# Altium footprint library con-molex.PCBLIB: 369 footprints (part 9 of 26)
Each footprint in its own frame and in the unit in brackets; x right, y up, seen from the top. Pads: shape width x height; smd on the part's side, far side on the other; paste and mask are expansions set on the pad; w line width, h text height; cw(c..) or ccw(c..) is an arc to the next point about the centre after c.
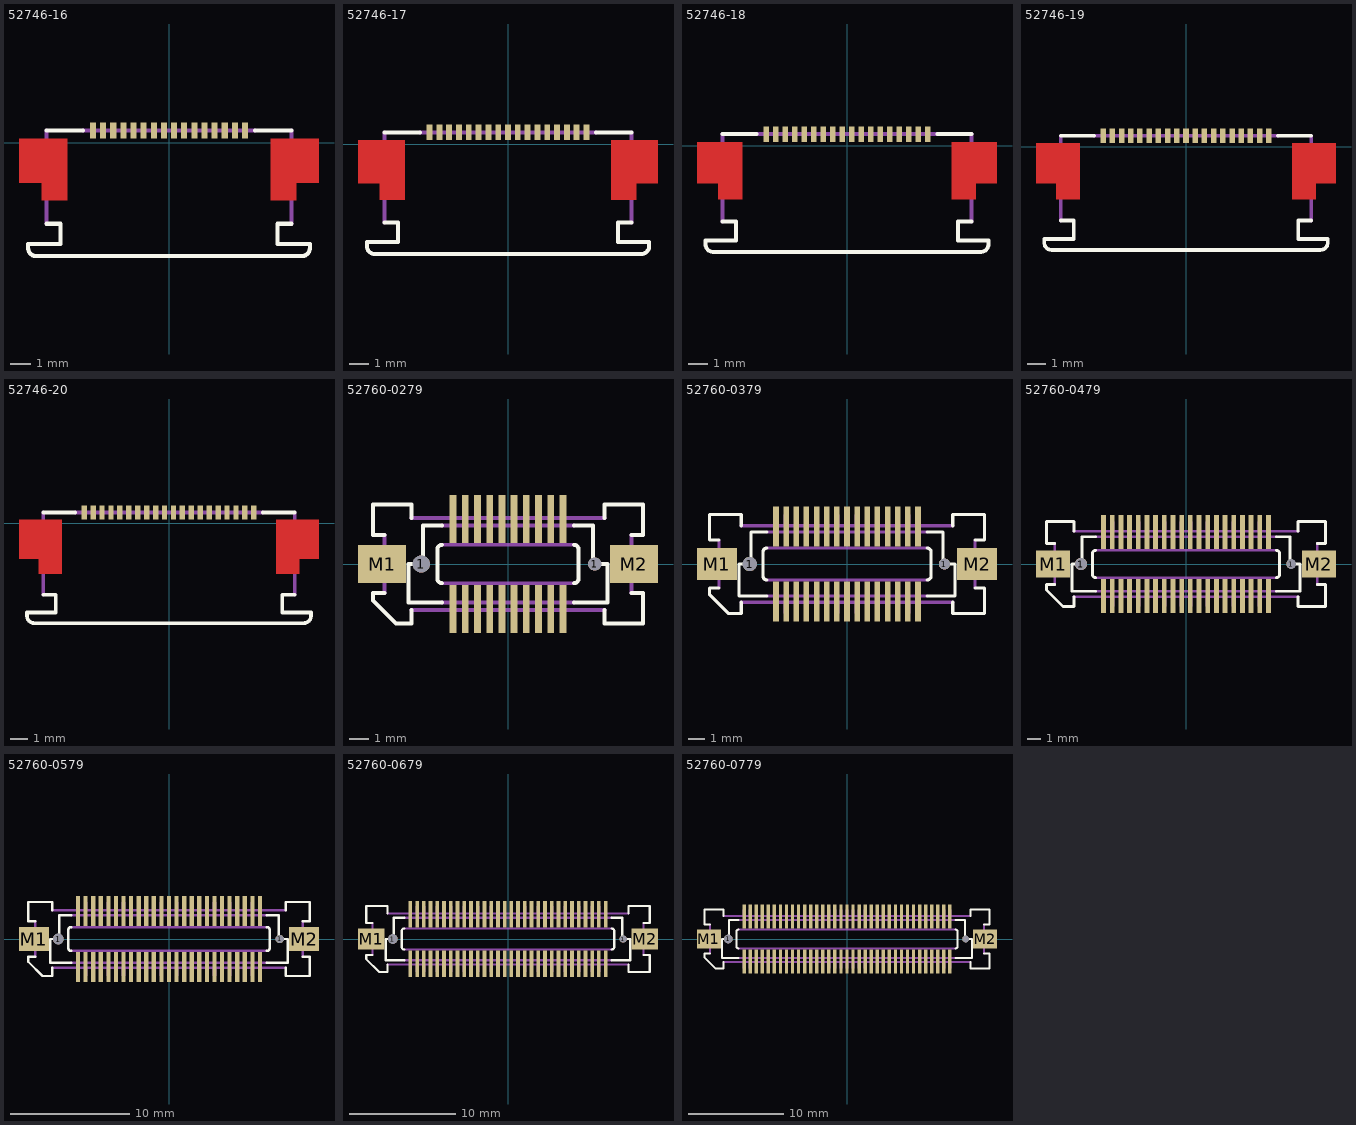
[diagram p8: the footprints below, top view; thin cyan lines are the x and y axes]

## 52746-16 [mil]
pads (16):
  rect 11.81x31.5 smd: 1(-147.64,23.62) 2(-127.95,23.62) 3(-108.27,23.62) 4(-88.58,23.62) 5(-68.9,23.62) 6(-49.21,23.62) 7(-29.53,23.62) 8(-9.84,23.62) 9(9.84,23.62) 10(29.53,23.62) 11(49.21,23.62) 12(68.9,23.62) 13(88.58,23.62) 14(108.27,23.62) 15(127.95,23.62) 16(147.64,23.62)
Top Layer:
  rectangle: -291.34,-78.74 -196.85,7.87
  rectangle: -248.03,-112.2 -196.85,-78.74
  rectangle: 196.85,-78.74 291.34,7.87
  rectangle: 196.85,-112.2 248.03,-78.74
Top Overlay:
  lines w8: -238.19,-157.48 -210.63,-157.48 -210.63,-196.85 -273.62,-196.85 -273.62,-204.72 ccw(c-257.87,-204.72) -257.87,-220.47 257.87,-220.47 ccw(c257.87,-204.72) 273.62,-204.72 273.62,-196.85 210.63,-196.85 210.63,-157.48 238.19,-157.48 ; -238.19,23.62 -167.32,23.62 ; 167.32,23.62 238.19,23.62
Top Paste:
  rectangle: -286.42,-74.8 -200.79,2.95
  rectangle: -244.09,-108.27 -200.79,-74.8
  rectangle: 200.79,-74.8 286.42,2.95
  rectangle: 200.79,-108.27 244.09,-74.8
Top Solder:
  rectangle: -291.34,-78.74 -196.85,7.87
  rectangle: -248.03,-112.2 -196.85,-78.74
  rectangle: 196.85,-78.74 291.34,7.87
  rectangle: 196.85,-112.2 248.03,-78.74
  rectangle: -154.53,6.89 -140.75,40.35
  rectangle: -134.84,6.89 -121.06,40.35
  rectangle: -115.16,6.89 -101.38,40.35
  rectangle: -95.47,6.89 -81.69,40.35
  rectangle: -75.79,6.89 -62.01,40.35
  rectangle: -56.1,6.89 -42.32,40.35
  rectangle: -36.42,6.89 -22.64,40.35
  rectangle: -16.73,6.89 -2.95,40.35
  rectangle: 2.95,6.89 16.73,40.35
  rectangle: 22.64,6.89 36.42,40.35
  rectangle: 42.32,6.89 56.1,40.35
  rectangle: 62.01,6.89 75.79,40.35
  rectangle: 81.69,6.89 95.47,40.35
  rectangle: 101.38,6.89 115.16,40.35
  rectangle: 121.06,6.89 134.84,40.35
  rectangle: 140.75,6.89 154.53,40.35
Mechanical 16:
  lines w8: -238.19,-157.48 -238.19,23.62 ; -167.32,23.62 167.32,23.62 ; 238.19,-157.48 238.19,23.62
  lines w19.69: -275.59,-55.12 -244.09,-55.12 -244.09,-9.84 -275.59,-9.84 ; 275.59,-55.12 244.09,-55.12 244.09,-9.84 275.59,-9.84

## 52746-17 [mil]
pads (17):
  rect 11.81x31.5 smd: 1(-157.48,23.62) 2(-137.8,23.62) 3(-118.11,23.62) 4(-98.43,23.62) 5(-78.74,23.62) 6(-59.06,23.62) 7(-39.37,23.62) 8(-19.69,23.62) 9(0,23.62) 10(19.69,23.62) 11(39.37,23.62) 12(59.06,23.62) 13(78.74,23.62) 14(98.43,23.62) 15(118.11,23.62) 16(137.8,23.62) 17(157.48,23.62)
Top Layer:
  rectangle: -301.18,-78.74 -206.69,7.87
  rectangle: -257.87,-112.2 -206.69,-78.74
  rectangle: 206.69,-78.74 301.18,7.87
  rectangle: 206.69,-112.2 257.87,-78.74
Top Overlay:
  lines w8: -248.03,-157.48 -220.47,-157.48 -220.47,-196.85 -283.46,-196.85 -283.46,-204.72 ccw(c-267.71,-204.72) -267.72,-220.47 267.72,-220.47 ccw(c267.71,-204.72) 283.46,-204.72 283.46,-196.85 220.47,-196.85 220.47,-157.48 248.03,-157.48 ; -248.03,23.62 -177.17,23.62 ; 177.17,23.62 248.03,23.62
Top Paste:
  rectangle: -296.26,-74.8 -210.63,2.95
  rectangle: -253.94,-108.27 -210.63,-74.8
  rectangle: 210.63,-74.8 296.26,2.95
  rectangle: 210.63,-108.27 253.94,-74.8
Top Solder:
  rectangle: -301.18,-78.74 -206.69,7.87
  rectangle: -257.87,-112.2 -206.69,-78.74
  rectangle: 206.69,-78.74 301.18,7.87
  rectangle: 206.69,-112.2 257.87,-78.74
  rectangle: -164.37,6.89 -150.59,40.35
  rectangle: -144.69,6.89 -130.91,40.35
  rectangle: -125,6.89 -111.22,40.35
  rectangle: -105.32,6.89 -91.54,40.35
  rectangle: -85.63,6.89 -71.85,40.35
  rectangle: -65.94,6.89 -52.17,40.35
  rectangle: -46.26,6.89 -32.48,40.35
  rectangle: -26.57,6.89 -12.8,40.35
  rectangle: -6.89,6.89 6.89,40.35
  rectangle: 12.8,6.89 26.57,40.35
  rectangle: 32.48,6.89 46.26,40.35
  rectangle: 52.17,6.89 65.94,40.35
  rectangle: 71.85,6.89 85.63,40.35
  rectangle: 91.54,6.89 105.32,40.35
  rectangle: 111.22,6.89 125,40.35
  rectangle: 130.91,6.89 144.69,40.35
  rectangle: 150.59,6.89 164.37,40.35
Mechanical 16:
  lines w8: -248.03,-157.48 -248.03,23.62 ; -177.17,23.62 177.17,23.62 ; 248.03,-157.48 248.03,23.62
  lines w19.69: -285.43,-55.12 -253.94,-55.12 -253.94,-9.84 -285.43,-9.84 ; 285.43,-55.12 253.94,-55.12 253.94,-9.84 285.43,-9.84

## 52746-18 [mil]
pads (18):
  rect 11.81x31.5 smd: 1(-167.32,23.62) 2(-147.64,23.62) 3(-127.95,23.62) 4(-108.27,23.62) 5(-88.58,23.62) 6(-68.9,23.62) 7(-49.21,23.62) 8(-29.53,23.62) 9(-9.84,23.62) 10(9.84,23.62) 11(29.53,23.62) 12(49.21,23.62) 13(68.9,23.62) 14(88.58,23.62) 15(108.27,23.62) 16(127.95,23.62) 17(147.64,23.62) 18(167.32,23.62)
Top Layer:
  rectangle: -311.02,-78.74 -216.54,7.87
  rectangle: -267.72,-112.2 -216.54,-78.74
  rectangle: 216.54,-78.74 311.02,7.87
  rectangle: 216.54,-112.2 267.72,-78.74
Top Overlay:
  lines w8: -257.87,-157.48 -230.32,-157.48 -230.32,-196.85 -293.31,-196.85 -293.31,-204.72 ccw(c-277.56,-204.72) -277.56,-220.47 277.56,-220.47 ccw(c277.56,-204.72) 293.31,-204.72 293.31,-196.85 230.32,-196.85 230.32,-157.48 257.87,-157.48 ; -257.87,23.62 -187.01,23.62 ; 187.01,23.62 257.87,23.62
Top Paste:
  rectangle: -306.1,-74.8 -220.47,2.95
  rectangle: -263.78,-108.27 -220.47,-74.8
  rectangle: 220.47,-74.8 306.1,2.95
  rectangle: 220.47,-108.27 263.78,-74.8
Top Solder:
  rectangle: -311.02,-78.74 -216.54,7.87
  rectangle: -267.72,-112.2 -216.54,-78.74
  rectangle: 216.54,-78.74 311.02,7.87
  rectangle: 216.54,-112.2 267.72,-78.74
  rectangle: -174.21,6.89 -160.43,40.35
  rectangle: -154.53,6.89 -140.75,40.35
  rectangle: -134.84,6.89 -121.06,40.35
  rectangle: -115.16,6.89 -101.38,40.35
  rectangle: -95.47,6.89 -81.69,40.35
  rectangle: -75.79,6.89 -62.01,40.35
  rectangle: -56.1,6.89 -42.32,40.35
  rectangle: -36.42,6.89 -22.64,40.35
  rectangle: -16.73,6.89 -2.95,40.35
  rectangle: 2.95,6.89 16.73,40.35
  rectangle: 22.64,6.89 36.42,40.35
  rectangle: 42.32,6.89 56.1,40.35
  rectangle: 62.01,6.89 75.79,40.35
  rectangle: 81.69,6.89 95.47,40.35
  rectangle: 101.38,6.89 115.16,40.35
  rectangle: 121.06,6.89 134.84,40.35
  rectangle: 140.75,6.89 154.53,40.35
  rectangle: 160.43,6.89 174.21,40.35
Mechanical 16:
  lines w8: -257.87,-157.48 -257.87,23.62 ; -187.01,23.62 187.01,23.62 ; 257.87,-157.48 257.87,23.62
  lines w19.69: -295.28,-55.12 -263.78,-55.12 -263.78,-9.84 -295.28,-9.84 ; 295.28,-55.12 263.78,-55.12 263.78,-9.84 295.28,-9.84

## 52746-19 [mil]
pads (19):
  rect 11.81x31.5 smd: 1(-177.17,23.62) 2(-157.48,23.62) 3(-137.8,23.62) 4(-118.11,23.62) 5(-98.43,23.62) 6(-78.74,23.62) 7(-59.06,23.62) 8(-39.37,23.62) 9(-19.69,23.62) 10(0,23.62) 11(19.69,23.62) 12(39.37,23.62) 13(59.06,23.62) 14(78.74,23.62) 15(98.43,23.62) 16(118.11,23.62) 17(137.8,23.62) 18(157.48,23.62) 19(177.17,23.62)
Top Layer:
  rectangle: -320.87,-78.74 -226.38,7.87
  rectangle: -277.56,-112.2 -226.38,-78.74
  rectangle: 226.38,-78.74 320.87,7.87
  rectangle: 226.38,-112.2 277.56,-78.74
Top Overlay:
  lines w8: -267.72,-157.48 -240.16,-157.48 -240.16,-196.85 -303.15,-196.85 -303.15,-204.72 ccw(c-287.4,-204.72) -287.4,-220.47 287.4,-220.47 ccw(c287.4,-204.72) 303.15,-204.72 303.15,-196.85 240.16,-196.85 240.16,-157.48 267.72,-157.48 ; -267.72,23.62 -196.85,23.62 ; 196.85,23.62 267.72,23.62
Top Paste:
  rectangle: -315.94,-74.8 -230.32,2.95
  rectangle: -273.62,-108.27 -230.32,-74.8
  rectangle: 230.32,-74.8 315.94,2.95
  rectangle: 230.32,-108.27 273.62,-74.8
Top Solder:
  rectangle: -320.87,-78.74 -226.38,7.87
  rectangle: -277.56,-112.2 -226.38,-78.74
  rectangle: 226.38,-78.74 320.87,7.87
  rectangle: 226.38,-112.2 277.56,-78.74
  rectangle: -184.06,6.89 -170.28,40.35
  rectangle: -164.37,6.89 -150.59,40.35
  rectangle: -144.69,6.89 -130.91,40.35
  rectangle: -125,6.89 -111.22,40.35
  rectangle: -105.32,6.89 -91.54,40.35
  rectangle: -85.63,6.89 -71.85,40.35
  rectangle: -65.94,6.89 -52.17,40.35
  rectangle: -46.26,6.89 -32.48,40.35
  rectangle: -26.57,6.89 -12.8,40.35
  rectangle: -6.89,6.89 6.89,40.35
  rectangle: 12.8,6.89 26.57,40.35
  rectangle: 32.48,6.89 46.26,40.35
  rectangle: 52.17,6.89 65.94,40.35
  rectangle: 71.85,6.89 85.63,40.35
  rectangle: 91.54,6.89 105.32,40.35
  rectangle: 111.22,6.89 125,40.35
  rectangle: 130.91,6.89 144.69,40.35
  rectangle: 150.59,6.89 164.37,40.35
  rectangle: 170.28,6.89 184.06,40.35
Mechanical 16:
  lines w8: -267.72,-157.48 -267.72,23.62 ; -196.85,23.62 196.85,23.62 ; 267.72,-157.48 267.72,23.62
  lines w19.69: -305.12,-55.12 -273.62,-55.12 -273.62,-9.84 -305.12,-9.84 ; 305.12,-55.12 273.62,-55.12 273.62,-9.84 305.12,-9.84

## 52746-20 [mil]
pads (20):
  rect 11.81x31.5 smd: 1(-187.01,23.62) 2(-167.32,23.62) 3(-147.64,23.62) 4(-127.95,23.62) 5(-108.27,23.62) 6(-88.58,23.62) 7(-68.9,23.62) 8(-49.21,23.62) 9(-29.53,23.62) 10(-9.84,23.62) 11(9.84,23.62) 12(29.53,23.62) 13(49.21,23.62) 14(68.9,23.62) 15(88.58,23.62) 16(108.27,23.62) 17(127.95,23.62) 18(147.64,23.62) 19(167.32,23.62) 20(187.01,23.62)
Top Layer:
  rectangle: -330.71,-78.74 -236.22,7.87
  rectangle: -287.4,-112.2 -236.22,-78.74
  rectangle: 236.22,-78.74 330.71,7.87
  rectangle: 236.22,-112.2 287.4,-78.74
Top Overlay:
  lines w8: -277.56,-157.48 -250,-157.48 -250,-196.85 -312.99,-196.85 -312.99,-204.72 ccw(c-297.24,-204.72) -297.24,-220.47 297.24,-220.47 ccw(c297.24,-204.72) 312.99,-204.72 312.99,-196.85 250,-196.85 250,-157.48 277.56,-157.48 ; -277.56,23.62 -206.69,23.62 ; 206.69,23.62 277.56,23.62
Top Paste:
  rectangle: -325.79,-74.8 -240.16,2.95
  rectangle: -283.46,-108.27 -240.16,-74.8
  rectangle: 240.16,-74.8 325.79,2.95
  rectangle: 240.16,-108.27 283.46,-74.8
Top Solder:
  rectangle: -330.71,-78.74 -236.22,7.87
  rectangle: -287.4,-112.2 -236.22,-78.74
  rectangle: 236.22,-78.74 330.71,7.87
  rectangle: 236.22,-112.2 287.4,-78.74
  rectangle: -193.9,6.89 -180.12,40.35
  rectangle: -174.21,6.89 -160.43,40.35
  rectangle: -154.53,6.89 -140.75,40.35
  rectangle: -134.84,6.89 -121.06,40.35
  rectangle: -115.16,6.89 -101.38,40.35
  rectangle: -95.47,6.89 -81.69,40.35
  rectangle: -75.79,6.89 -62.01,40.35
  rectangle: -56.1,6.89 -42.32,40.35
  rectangle: -36.42,6.89 -22.64,40.35
  rectangle: -16.73,6.89 -2.95,40.35
  rectangle: 2.95,6.89 16.73,40.35
  rectangle: 22.64,6.89 36.42,40.35
  rectangle: 42.32,6.89 56.1,40.35
  rectangle: 62.01,6.89 75.79,40.35
  rectangle: 81.69,6.89 95.47,40.35
  rectangle: 101.38,6.89 115.16,40.35
  rectangle: 121.06,6.89 134.84,40.35
  rectangle: 140.75,6.89 154.53,40.35
  rectangle: 160.43,6.89 174.21,40.35
  rectangle: 180.12,6.89 193.9,40.35
Mechanical 16:
  lines w8: -277.56,-157.48 -277.56,23.62 ; -206.69,23.62 206.69,23.62 ; 277.56,-157.48 277.56,23.62
  lines w19.69: -314.96,-55.12 -283.46,-55.12 -283.46,-9.84 -314.96,-9.84 ; 314.96,-55.12 283.46,-55.12 283.46,-9.84 314.96,-9.84

## 52760-0279 [mm]
pads (24):
  round 0.9 hole 0.9: 1(-4.51,0)
  rect 0.35x2.5 smd: 1(-2.857,-2.35) 2(-2.857,2.35) 3(-2.222,-2.35) 4(-2.222,2.35) 5(-1.587,-2.35) 6(-1.587,2.35) 7(-0.953,-2.35) 8(-0.953,2.35) 9(-0.318,-2.35) 10(-0.318,2.35) 11(0.318,-2.35) 12(0.318,2.35) 13(0.953,-2.35) 14(0.953,2.35) 15(1.587,-2.35) 16(1.587,2.35) 17(2.222,-2.35) 18(2.222,2.35) 19(2.857,-2.35) 20(2.857,2.35)
  round 0.7 hole 0.7: 1(4.51,0)
  rect 2.5x2 smd: M1(-6.55,0) M2(6.55,0)
Top Overlay:
  lines w0.203: -6.425,-1.5 -7.025,-1.5 -7.025,-1.9 -5.825,-3.1 -5.025,-3.1 -5.025,-2.4 ; -6.425,1.5 -7.025,1.5 -7.025,3.1 -5.025,3.1 -5.025,2.4 ; -3.425,-2 -5.175,-2 -5.175,0 -4.425,0 -4.425,2 -3.425,2 ; -3.425,-1 cw(c-3.425,-0.75) -3.675,-0.75 -3.675,0.75 cw(c-3.425,0.75) -3.425,1 ; 3.425,-2 5.175,-2 5.175,0 4.425,0 4.425,2 3.425,2 ; 3.425,-1 ccw(c3.425,-0.75) 3.675,-0.75 3.675,0.75 ccw(c3.425,0.75) 3.425,1 ; 5.025,-2.4 5.025,-3.1 7.025,-3.1 7.025,-1.5 6.425,-1.5 ; 5.025,2.4 5.025,3.1 7.025,3.1 7.025,1.5 6.425,1.5
Top Solder:
  rectangle: -3.057,-3.625 -2.658,-1.075
  region: -2.658,3.625 -3.057,3.625 -3.057,1.075 -2.658,1.075
  rectangle: -2.422,-3.625 -2.023,-1.075
  region: -2.023,3.625 -2.422,3.625 -2.422,1.075 -2.023,1.075
  rectangle: -1.787,-3.625 -1.388,-1.075
  region: -1.388,3.625 -1.787,3.625 -1.787,1.075 -1.388,1.075
  rectangle: -1.152,-3.625 -0.753,-1.075
  region: -0.753,3.625 -1.152,3.625 -1.152,1.075 -0.753,1.075
  rectangle: -0.517,-3.625 -0.118,-1.075
  region: -0.118,3.625 -0.517,3.625 -0.517,1.075 -0.118,1.075
  rectangle: 0.118,-3.625 0.517,-1.075
  region: 0.517,3.625 0.118,3.625 0.118,1.075 0.517,1.075
  rectangle: 0.753,-3.625 1.152,-1.075
  region: 1.152,3.625 0.753,3.625 0.753,1.075 1.152,1.075
  rectangle: 1.388,-3.625 1.787,-1.075
  region: 1.787,3.625 1.388,3.625 1.388,1.075 1.787,1.075
  rectangle: 2.023,-3.625 2.422,-1.075
  region: 2.422,3.625 2.023,3.625 2.023,1.075 2.422,1.075
  rectangle: 2.658,-3.625 3.057,-1.075
  region: 3.057,3.625 2.658,3.625 2.658,1.075 3.057,1.075
Mechanical 16:
  rectangle: -3.008,-3.1 -2.707,-2.375
  region: -2.707,3.1 -3.008,3.1 -3.008,2.375 -2.707,2.375
  rectangle: -2.373,-3.1 -2.072,-2.375
  region: -2.072,3.1 -2.373,3.1 -2.373,2.375 -2.072,2.375
  rectangle: -1.738,-3.1 -1.437,-2.375
  region: -1.437,3.1 -1.738,3.1 -1.738,2.375 -1.437,2.375
  rectangle: -1.103,-3.1 -0.802,-2.375
  region: -0.802,3.1 -1.103,3.1 -1.103,2.375 -0.802,2.375
  rectangle: -0.468,-3.1 -0.167,-2.375
  region: -0.167,3.1 -0.468,3.1 -0.468,2.375 -0.167,2.375
  rectangle: 0.167,-3.1 0.468,-2.375
  region: 0.468,3.1 0.167,3.1 0.167,2.375 0.468,2.375
  rectangle: 0.802,-3.1 1.103,-2.375
  region: 1.103,3.1 0.802,3.1 0.802,2.375 1.103,2.375
  rectangle: 1.437,-3.1 1.738,-2.375
  region: 1.738,3.1 1.437,3.1 1.437,2.375 1.738,2.375
  rectangle: 2.072,-3.1 2.373,-2.375
  region: 2.373,3.1 2.072,3.1 2.072,2.375 2.373,2.375
  rectangle: 2.707,-3.1 3.008,-2.375
  region: 3.008,3.1 2.707,3.1 2.707,2.375 3.008,2.375
  lines w0.203: -6.425,-1.5 -6.425,1.5 ; -5.025,-2.4 5.025,-2.4 ; -5.025,2.4 5.025,2.4 ; -3.425,-2 3.425,-2 ; -3.425,-1 3.425,-1 ; -3.425,1 3.425,1 ; -3.425,2 3.425,2 ; 6.425,-1.5 6.425,1.5

## 52760-0379 [mm]
pads (34):
  round 0.9 hole 0.9: 1(-6.098,0)
  rect 0.35x2.5 smd: 1(-4.445,-2.35) 2(-4.445,2.35) 3(-3.81,-2.35) 4(-3.81,2.35) 5(-3.175,-2.35) 6(-3.175,2.35) 7(-2.54,-2.35) 8(-2.54,2.35) 9(-1.905,-2.35) 10(-1.905,2.35) 11(-1.27,-2.35) 12(-1.27,2.35) 13(-0.635,-2.35) 14(-0.635,2.35) 15(0,-2.35) 16(0,2.35) 17(0.635,-2.35) 18(0.635,2.35) 19(1.27,-2.35) 20(1.27,2.35) 21(1.905,-2.35) 22(1.905,2.35) 23(2.54,-2.35) 24(2.54,2.35) 25(3.175,-2.35) 26(3.175,2.35) 27(3.81,-2.35) 28(3.81,2.35) 29(4.445,-2.35) 30(4.445,2.35)
  round 0.7 hole 0.7: 1(6.098,0)
  rect 2.5x2 smd: M1(-8.137,0) M2(8.137,0)
Top Overlay:
  lines w0.203: -8.012,-1.5 -8.612,-1.5 -8.612,-1.9 -7.412,-3.1 -6.612,-3.1 -6.612,-2.4 ; -8.012,1.5 -8.612,1.5 -8.612,3.1 -6.612,3.1 -6.612,2.4 ; -5.012,-2 -6.762,-2 -6.762,0 -6.012,0 -6.012,2 -5.012,2 ; -5.012,-1 cw(c-5.013,-0.75) -5.263,-0.75 -5.263,0.75 cw(c-5.013,0.75) -5.012,1 ; 5.012,-2 6.762,-2 6.762,0 6.012,0 6.012,2 5.012,2 ; 5.012,-1 ccw(c5.013,-0.75) 5.263,-0.75 5.263,0.75 ccw(c5.013,0.75) 5.012,1 ; 6.612,-2.4 6.612,-3.1 8.612,-3.1 8.612,-1.5 8.012,-1.5 ; 6.612,2.4 6.612,3.1 8.612,3.1 8.612,1.5 8.012,1.5
Top Solder:
  region: 4.645,3.625 4.245,3.625 4.245,1.075 4.645,1.075
  rectangle: 4.245,-3.625 4.645,-1.075
  region: 4.01,3.625 3.61,3.625 3.61,1.075 4.01,1.075
  rectangle: 3.61,-3.625 4.01,-1.075
  region: 3.375,3.625 2.975,3.625 2.975,1.075 3.375,1.075
  rectangle: 2.975,-3.625 3.375,-1.075
  region: 2.74,3.625 2.34,3.625 2.34,1.075 2.74,1.075
  rectangle: 2.34,-3.625 2.74,-1.075
  region: 2.105,3.625 1.705,3.625 1.705,1.075 2.105,1.075
  rectangle: 1.705,-3.625 2.105,-1.075
  region: 1.47,3.625 1.07,3.625 1.07,1.075 1.47,1.075
  rectangle: 1.07,-3.625 1.47,-1.075
  region: 0.835,3.625 0.435,3.625 0.435,1.075 0.835,1.075
  rectangle: 0.435,-3.625 0.835,-1.075
  region: 0.2,3.625 -0.2,3.625 -0.2,1.075 0.2,1.075
  rectangle: -0.2,-3.625 0.2,-1.075
  region: -0.435,3.625 -0.835,3.625 -0.835,1.075 -0.435,1.075
  rectangle: -0.835,-3.625 -0.435,-1.075
  region: -1.07,3.625 -1.47,3.625 -1.47,1.075 -1.07,1.075
  rectangle: -1.47,-3.625 -1.07,-1.075
  region: -1.705,3.625 -2.105,3.625 -2.105,1.075 -1.705,1.075
  rectangle: -2.105,-3.625 -1.705,-1.075
  region: -2.34,3.625 -2.74,3.625 -2.74,1.075 -2.34,1.075
  rectangle: -2.74,-3.625 -2.34,-1.075
  region: -2.975,3.625 -3.375,3.625 -3.375,1.075 -2.975,1.075
  rectangle: -3.375,-3.625 -2.975,-1.075
  region: -3.61,3.625 -4.01,3.625 -4.01,1.075 -3.61,1.075
  rectangle: -4.01,-3.625 -3.61,-1.075
  region: -4.245,3.625 -4.645,3.625 -4.645,1.075 -4.245,1.075
  rectangle: -4.645,-3.625 -4.245,-1.075
Mechanical 16:
  region: 4.595,3.1 4.295,3.1 4.295,2.375 4.595,2.375
  rectangle: 4.295,-3.1 4.595,-2.375
  region: 3.96,3.1 3.66,3.1 3.66,2.375 3.96,2.375
  rectangle: 3.66,-3.1 3.96,-2.375
  region: 3.325,3.1 3.025,3.1 3.025,2.375 3.325,2.375
  rectangle: 3.025,-3.1 3.325,-2.375
  region: 2.69,3.1 2.39,3.1 2.39,2.375 2.69,2.375
  rectangle: 2.39,-3.1 2.69,-2.375
  region: 2.055,3.1 1.755,3.1 1.755,2.375 2.055,2.375
  rectangle: 1.755,-3.1 2.055,-2.375
  region: 1.42,3.1 1.12,3.1 1.12,2.375 1.42,2.375
  rectangle: 1.12,-3.1 1.42,-2.375
  region: 0.785,3.1 0.485,3.1 0.485,2.375 0.785,2.375
  rectangle: 0.485,-3.1 0.785,-2.375
  region: 0.15,3.1 -0.15,3.1 -0.15,2.375 0.15,2.375
  rectangle: -0.15,-3.1 0.15,-2.375
  region: -0.485,3.1 -0.785,3.1 -0.785,2.375 -0.485,2.375
  rectangle: -0.785,-3.1 -0.485,-2.375
  region: -1.12,3.1 -1.42,3.1 -1.42,2.375 -1.12,2.375
  rectangle: -1.42,-3.1 -1.12,-2.375
  region: -1.755,3.1 -2.055,3.1 -2.055,2.375 -1.755,2.375
  rectangle: -2.055,-3.1 -1.755,-2.375
  region: -2.39,3.1 -2.69,3.1 -2.69,2.375 -2.39,2.375
  rectangle: -2.69,-3.1 -2.39,-2.375
  region: -3.025,3.1 -3.325,3.1 -3.325,2.375 -3.025,2.375
  rectangle: -3.325,-3.1 -3.025,-2.375
  region: -3.66,3.1 -3.96,3.1 -3.96,2.375 -3.66,2.375
  rectangle: -3.96,-3.1 -3.66,-2.375
  region: -4.295,3.1 -4.595,3.1 -4.595,2.375 -4.295,2.375
  rectangle: -4.595,-3.1 -4.295,-2.375
  lines w0.203: -8.012,-1.5 -8.012,1.5 ; -6.612,-2.4 6.612,-2.4 ; -6.612,2.4 6.612,2.4 ; -5.012,-2 5.012,-2 ; -5.012,-1 5.012,-1 ; -5.012,1 5.012,1 ; -5.012,2 5.012,2 ; 8.012,-1.5 8.012,1.5

## 52760-0479 [mm]
pads (44):
  round 0.9 hole 0.9: 1(-7.685,0)
  rect 0.35x2.5 smd: 1(-6.032,-2.35) 2(-6.032,2.35) 3(-5.397,-2.35) 4(-5.397,2.35) 5(-4.763,-2.35) 6(-4.763,2.35) 7(-4.127,-2.35) 8(-4.127,2.35) 9(-3.492,-2.35) 10(-3.492,2.35) 11(-2.857,-2.35) 12(-2.857,2.35) 13(-2.222,-2.35) 14(-2.222,2.35) 15(-1.587,-2.35) 16(-1.587,2.35) 17(-0.953,-2.35) 18(-0.953,2.35) 19(-0.318,-2.35) 20(-0.318,2.35) 21(0.318,-2.35) 22(0.318,2.35) 23(0.953,-2.35) 24(0.953,2.35) 25(1.587,-2.35) 26(1.587,2.35) 27(2.222,-2.35) 28(2.222,2.35) 29(2.857,-2.35) 30(2.857,2.35) 31(3.492,-2.35) 32(3.492,2.35) 33(4.127,-2.35) 34(4.127,2.35) 35(4.763,-2.35) 36(4.763,2.35) 37(5.397,-2.35) 38(5.397,2.35) 39(6.032,-2.35) 40(6.032,2.35)
  round 0.7 hole 0.7: 1(7.685,0)
  rect 2.5x2 smd: M1(-9.725,0) M2(9.725,0)
Top Overlay:
  lines w0.203: -9.6,-1.5 -10.2,-1.5 -10.2,-1.9 -9,-3.1 -8.2,-3.1 -8.2,-2.4 ; -9.6,1.5 -10.2,1.5 -10.2,3.1 -8.2,3.1 -8.2,2.4 ; -6.6,-2 -8.35,-2 -8.35,0 -7.6,0 -7.6,2 -6.6,2 ; -6.6,-1 cw(c-6.6,-0.75) -6.85,-0.75 -6.85,0.75 cw(c-6.6,0.75) -6.6,1 ; 6.6,-2 8.35,-2 8.35,0 7.6,0 7.6,2 6.6,2 ; 6.6,-1 ccw(c6.6,-0.75) 6.85,-0.75 6.85,0.75 ccw(c6.6,0.75) 6.6,1 ; 8.2,-2.4 8.2,-3.1 10.2,-3.1 10.2,-1.5 9.6,-1.5 ; 8.2,2.4 8.2,3.1 10.2,3.1 10.2,1.5 9.6,1.5
Top Solder:
  rectangle: -6.232,-3.625 -5.833,-1.075
  region: -5.833,3.625 -6.232,3.625 -6.232,1.075 -5.833,1.075
  rectangle: -5.597,-3.625 -5.198,-1.075
  region: -5.198,3.625 -5.597,3.625 -5.597,1.075 -5.198,1.075
  rectangle: -4.962,-3.625 -4.563,-1.075
  region: -4.563,3.625 -4.962,3.625 -4.962,1.075 -4.563,1.075
  rectangle: -4.327,-3.625 -3.928,-1.075
  region: -3.928,3.625 -4.327,3.625 -4.327,1.075 -3.928,1.075
  rectangle: -3.692,-3.625 -3.293,-1.075
  region: -3.293,3.625 -3.692,3.625 -3.692,1.075 -3.293,1.075
  rectangle: -3.057,-3.625 -2.658,-1.075
  region: -2.658,3.625 -3.057,3.625 -3.057,1.075 -2.658,1.075
  rectangle: -2.422,-3.625 -2.023,-1.075
  region: -2.023,3.625 -2.422,3.625 -2.422,1.075 -2.023,1.075
  rectangle: -1.787,-3.625 -1.388,-1.075
  region: -1.388,3.625 -1.787,3.625 -1.787,1.075 -1.388,1.075
  rectangle: -1.152,-3.625 -0.753,-1.075
  region: -0.753,3.625 -1.152,3.625 -1.152,1.075 -0.753,1.075
  rectangle: -0.517,-3.625 -0.118,-1.075
  region: -0.118,3.625 -0.517,3.625 -0.517,1.075 -0.118,1.075
  rectangle: 0.118,-3.625 0.517,-1.075
  region: 0.517,3.625 0.118,3.625 0.118,1.075 0.517,1.075
  rectangle: 0.753,-3.625 1.152,-1.075
  region: 1.152,3.625 0.753,3.625 0.753,1.075 1.152,1.075
  rectangle: 1.388,-3.625 1.787,-1.075
  region: 1.787,3.625 1.388,3.625 1.388,1.075 1.787,1.075
  rectangle: 2.023,-3.625 2.422,-1.075
  region: 2.422,3.625 2.023,3.625 2.023,1.075 2.422,1.075
  rectangle: 2.658,-3.625 3.057,-1.075
  region: 3.057,3.625 2.658,3.625 2.658,1.075 3.057,1.075
  rectangle: 3.293,-3.625 3.692,-1.075
  region: 3.692,3.625 3.293,3.625 3.293,1.075 3.692,1.075
  rectangle: 3.928,-3.625 4.327,-1.075
  region: 4.327,3.625 3.928,3.625 3.928,1.075 4.327,1.075
  rectangle: 4.563,-3.625 4.962,-1.075
  region: 4.962,3.625 4.563,3.625 4.563,1.075 4.962,1.075
  rectangle: 5.198,-3.625 5.597,-1.075
  region: 5.597,3.625 5.198,3.625 5.198,1.075 5.597,1.075
  rectangle: 5.833,-3.625 6.232,-1.075
  region: 6.232,3.625 5.833,3.625 5.833,1.075 6.232,1.075
Mechanical 16:
  rectangle: -6.183,-3.1 -5.882,-2.375
  region: -5.882,3.1 -6.183,3.1 -6.183,2.375 -5.882,2.375
  rectangle: -5.548,-3.1 -5.247,-2.375
  region: -5.247,3.1 -5.548,3.1 -5.548,2.375 -5.247,2.375
  rectangle: -4.913,-3.1 -4.612,-2.375
  region: -4.612,3.1 -4.913,3.1 -4.913,2.375 -4.612,2.375
  rectangle: -4.278,-3.1 -3.977,-2.375
  region: -3.977,3.1 -4.278,3.1 -4.278,2.375 -3.977,2.375
  rectangle: -3.643,-3.1 -3.342,-2.375
  region: -3.342,3.1 -3.643,3.1 -3.643,2.375 -3.342,2.375
  rectangle: -3.008,-3.1 -2.707,-2.375
  region: -2.707,3.1 -3.008,3.1 -3.008,2.375 -2.707,2.375
  rectangle: -2.373,-3.1 -2.072,-2.375
  region: -2.072,3.1 -2.373,3.1 -2.373,2.375 -2.072,2.375
  rectangle: -1.738,-3.1 -1.437,-2.375
  region: -1.437,3.1 -1.738,3.1 -1.738,2.375 -1.437,2.375
  rectangle: -1.103,-3.1 -0.802,-2.375
  region: -0.802,3.1 -1.103,3.1 -1.103,2.375 -0.802,2.375
  rectangle: -0.468,-3.1 -0.167,-2.375
  region: -0.167,3.1 -0.468,3.1 -0.468,2.375 -0.167,2.375
  rectangle: 0.167,-3.1 0.468,-2.375
  region: 0.468,3.1 0.167,3.1 0.167,2.375 0.468,2.375
  rectangle: 0.802,-3.1 1.103,-2.375
  region: 1.103,3.1 0.802,3.1 0.802,2.375 1.103,2.375
  rectangle: 1.437,-3.1 1.738,-2.375
  region: 1.738,3.1 1.437,3.1 1.437,2.375 1.738,2.375
  rectangle: 2.072,-3.1 2.373,-2.375
  region: 2.373,3.1 2.072,3.1 2.072,2.375 2.373,2.375
  rectangle: 2.707,-3.1 3.008,-2.375
  region: 3.008,3.1 2.707,3.1 2.707,2.375 3.008,2.375
  rectangle: 3.342,-3.1 3.643,-2.375
  region: 3.643,3.1 3.342,3.1 3.342,2.375 3.643,2.375
  rectangle: 3.977,-3.1 4.278,-2.375
  region: 4.278,3.1 3.977,3.1 3.977,2.375 4.278,2.375
  rectangle: 4.612,-3.1 4.913,-2.375
  region: 4.913,3.1 4.612,3.1 4.612,2.375 4.913,2.375
  rectangle: 5.247,-3.1 5.548,-2.375
  region: 5.548,3.1 5.247,3.1 5.247,2.375 5.548,2.375
  rectangle: 5.882,-3.1 6.183,-2.375
  region: 6.183,3.1 5.882,3.1 5.882,2.375 6.183,2.375
  lines w0.203: -9.6,-1.5 -9.6,1.5 ; -8.2,-2.4 8.2,-2.4 ; -8.2,2.4 8.2,2.4 ; -6.6,-2 6.6,-2 ; -6.6,-1 6.6,-1 ; -6.6,1 6.6,1 ; -6.6,2 6.6,2 ; 9.6,-1.5 9.6,1.5

## 52760-0579 [mm]
pads (54):
  round 0.9 hole 0.9: 1(-9.273,0)
  rect 0.35x2.5 smd: 1(-7.62,-2.35) 2(-7.62,2.35) 3(-6.985,-2.35) 4(-6.985,2.35) 5(-6.35,-2.35) 6(-6.35,2.35) 7(-5.715,-2.35) 8(-5.715,2.35) 9(-5.08,-2.35) 10(-5.08,2.35) 11(-4.445,-2.35) 12(-4.445,2.35) 13(-3.81,-2.35) 14(-3.81,2.35) 15(-3.175,-2.35) 16(-3.175,2.35) 17(-2.54,-2.35) 18(-2.54,2.35) 19(-1.905,-2.35) 20(-1.905,2.35) 21(-1.27,-2.35) 22(-1.27,2.35) 23(-0.635,-2.35) 24(-0.635,2.35) 25(0,-2.35) 26(0,2.35) 27(0.635,-2.35) 28(0.635,2.35) 29(1.27,-2.35) 30(1.27,2.35) 31(1.905,-2.35) 32(1.905,2.35) 33(2.54,-2.35) 34(2.54,2.35) 35(3.175,-2.35) 36(3.175,2.35) 37(3.81,-2.35) 38(3.81,2.35) 39(4.445,-2.35) 40(4.445,2.35) 41(5.08,-2.35) 42(5.08,2.35) 43(5.715,-2.35) 44(5.715,2.35) 45(6.35,-2.35) 46(6.35,2.35) 47(6.985,-2.35) 48(6.985,2.35) 49(7.62,-2.35) 50(7.62,2.35)
  round 0.7 hole 0.7: 1(9.273,0)
  rect 2.5x2 smd: M1(-11.312,0) M2(11.312,0)
Top Overlay:
  lines w0.203: -11.187,-1.5 -11.787,-1.5 -11.787,-1.9 -10.587,-3.1 -9.787,-3.1 -9.787,-2.4 ; -11.187,1.5 -11.787,1.5 -11.787,3.1 -9.787,3.1 -9.787,2.4 ; -8.187,-2 -9.937,-2 -9.937,0 -9.187,0 -9.187,2 -8.187,2 ; -8.187,-1 cw(c-8.188,-0.75) -8.438,-0.75 -8.438,0.75 cw(c-8.188,0.75) -8.187,1 ; 8.187,-2 9.937,-2 9.937,0 9.187,0 9.187,2 8.187,2 ; 8.187,-1 ccw(c8.188,-0.75) 8.438,-0.75 8.438,0.75 ccw(c8.188,0.75) 8.187,1 ; 9.787,-2.4 9.787,-3.1 11.787,-3.1 11.787,-1.5 11.187,-1.5 ; 9.787,2.4 9.787,3.1 11.787,3.1 11.787,1.5 11.187,1.5
Top Solder:
  rectangle: -7.82,-3.625 -7.42,-1.075
  region: -7.42,3.625 -7.82,3.625 -7.82,1.075 -7.42,1.075
  rectangle: -7.185,-3.625 -6.785,-1.075
  region: -6.785,3.625 -7.185,3.625 -7.185,1.075 -6.785,1.075
  rectangle: -6.55,-3.625 -6.15,-1.075
  region: -6.15,3.625 -6.55,3.625 -6.55,1.075 -6.15,1.075
  rectangle: -5.915,-3.625 -5.515,-1.075
  region: -5.515,3.625 -5.915,3.625 -5.915,1.075 -5.515,1.075
  rectangle: -5.28,-3.625 -4.88,-1.075
  region: -4.88,3.625 -5.28,3.625 -5.28,1.075 -4.88,1.075
  rectangle: -4.645,-3.625 -4.245,-1.075
  region: -4.245,3.625 -4.645,3.625 -4.645,1.075 -4.245,1.075
  rectangle: -4.01,-3.625 -3.61,-1.075
  region: -3.61,3.625 -4.01,3.625 -4.01,1.075 -3.61,1.075
  rectangle: -3.375,-3.625 -2.975,-1.075
  region: -2.975,3.625 -3.375,3.625 -3.375,1.075 -2.975,1.075
  rectangle: -2.74,-3.625 -2.34,-1.075
  region: -2.34,3.625 -2.74,3.625 -2.74,1.075 -2.34,1.075
  rectangle: -2.105,-3.625 -1.705,-1.075
  region: -1.705,3.625 -2.105,3.625 -2.105,1.075 -1.705,1.075
  rectangle: -1.47,-3.625 -1.07,-1.075
  region: -1.07,3.625 -1.47,3.625 -1.47,1.075 -1.07,1.075
  rectangle: -0.835,-3.625 -0.435,-1.075
  region: -0.435,3.625 -0.835,3.625 -0.835,1.075 -0.435,1.075
  rectangle: -0.2,-3.625 0.2,-1.075
  region: 0.2,3.625 -0.2,3.625 -0.2,1.075 0.2,1.075
  rectangle: 0.435,-3.625 0.835,-1.075
  region: 0.835,3.625 0.435,3.625 0.435,1.075 0.835,1.075
  rectangle: 1.07,-3.625 1.47,-1.075
  region: 1.47,3.625 1.07,3.625 1.07,1.075 1.47,1.075
  rectangle: 1.705,-3.625 2.105,-1.075
  region: 2.105,3.625 1.705,3.625 1.705,1.075 2.105,1.075
  rectangle: 2.34,-3.625 2.74,-1.075
  region: 2.74,3.625 2.34,3.625 2.34,1.075 2.74,1.075
  rectangle: 2.975,-3.625 3.375,-1.075
  region: 3.375,3.625 2.975,3.625 2.975,1.075 3.375,1.075
  rectangle: 3.61,-3.625 4.01,-1.075
  region: 4.01,3.625 3.61,3.625 3.61,1.075 4.01,1.075
  rectangle: 4.245,-3.625 4.645,-1.075
  region: 4.645,3.625 4.245,3.625 4.245,1.075 4.645,1.075
  rectangle: 4.88,-3.625 5.28,-1.075
  region: 5.28,3.625 4.88,3.625 4.88,1.075 5.28,1.075
  rectangle: 5.515,-3.625 5.915,-1.075
  region: 5.915,3.625 5.515,3.625 5.515,1.075 5.915,1.075
  rectangle: 6.15,-3.625 6.55,-1.075
  region: 6.55,3.625 6.15,3.625 6.15,1.075 6.55,1.075
  rectangle: 6.785,-3.625 7.185,-1.075
  region: 7.185,3.625 6.785,3.625 6.785,1.075 7.185,1.075
  rectangle: 7.42,-3.625 7.82,-1.075
  region: 7.82,3.625 7.42,3.625 7.42,1.075 7.82,1.075
Mechanical 16:
  rectangle: -7.77,-3.1 -7.47,-2.375
  region: -7.47,3.1 -7.77,3.1 -7.77,2.375 -7.47,2.375
  rectangle: -7.135,-3.1 -6.835,-2.375
  region: -6.835,3.1 -7.135,3.1 -7.135,2.375 -6.835,2.375
  rectangle: -6.5,-3.1 -6.2,-2.375
  region: -6.2,3.1 -6.5,3.1 -6.5,2.375 -6.2,2.375
  rectangle: -5.865,-3.1 -5.565,-2.375
  region: -5.565,3.1 -5.865,3.1 -5.865,2.375 -5.565,2.375
  rectangle: -5.23,-3.1 -4.93,-2.375
  region: -4.93,3.1 -5.23,3.1 -5.23,2.375 -4.93,2.375
  rectangle: -4.595,-3.1 -4.295,-2.375
  region: -4.295,3.1 -4.595,3.1 -4.595,2.375 -4.295,2.375
  rectangle: -3.96,-3.1 -3.66,-2.375
  region: -3.66,3.1 -3.96,3.1 -3.96,2.375 -3.66,2.375
  rectangle: -3.325,-3.1 -3.025,-2.375
  region: -3.025,3.1 -3.325,3.1 -3.325,2.375 -3.025,2.375
  rectangle: -2.69,-3.1 -2.39,-2.375
  region: -2.39,3.1 -2.69,3.1 -2.69,2.375 -2.39,2.375
  rectangle: -2.055,-3.1 -1.755,-2.375
  region: -1.755,3.1 -2.055,3.1 -2.055,2.375 -1.755,2.375
  rectangle: -1.42,-3.1 -1.12,-2.375
  region: -1.12,3.1 -1.42,3.1 -1.42,2.375 -1.12,2.375
  rectangle: -0.785,-3.1 -0.485,-2.375
  region: -0.485,3.1 -0.785,3.1 -0.785,2.375 -0.485,2.375
  rectangle: -0.15,-3.1 0.15,-2.375
  region: 0.15,3.1 -0.15,3.1 -0.15,2.375 0.15,2.375
  rectangle: 0.485,-3.1 0.785,-2.375
  region: 0.785,3.1 0.485,3.1 0.485,2.375 0.785,2.375
  rectangle: 1.12,-3.1 1.42,-2.375
  region: 1.42,3.1 1.12,3.1 1.12,2.375 1.42,2.375
  rectangle: 1.755,-3.1 2.055,-2.375
  region: 2.055,3.1 1.755,3.1 1.755,2.375 2.055,2.375
  rectangle: 2.39,-3.1 2.69,-2.375
  region: 2.69,3.1 2.39,3.1 2.39,2.375 2.69,2.375
  rectangle: 3.025,-3.1 3.325,-2.375
  region: 3.325,3.1 3.025,3.1 3.025,2.375 3.325,2.375
  rectangle: 3.66,-3.1 3.96,-2.375
  region: 3.96,3.1 3.66,3.1 3.66,2.375 3.96,2.375
  rectangle: 4.295,-3.1 4.595,-2.375
  region: 4.595,3.1 4.295,3.1 4.295,2.375 4.595,2.375
  rectangle: 4.93,-3.1 5.23,-2.375
  region: 5.23,3.1 4.93,3.1 4.93,2.375 5.23,2.375
  rectangle: 5.565,-3.1 5.865,-2.375
  region: 5.865,3.1 5.565,3.1 5.565,2.375 5.865,2.375
  rectangle: 6.2,-3.1 6.5,-2.375
  region: 6.5,3.1 6.2,3.1 6.2,2.375 6.5,2.375
  rectangle: 6.835,-3.1 7.135,-2.375
  region: 7.135,3.1 6.835,3.1 6.835,2.375 7.135,2.375
  rectangle: 7.47,-3.1 7.77,-2.375
  region: 7.77,3.1 7.47,3.1 7.47,2.375 7.77,2.375
  lines w0.203: -11.187,-1.5 -11.187,1.5 ; -9.787,-2.4 9.787,-2.4 ; -9.787,2.4 9.787,2.4 ; -8.187,-2 8.187,-2 ; -8.187,-1 8.187,-1 ; -8.187,1 8.187,1 ; -8.187,2 8.187,2 ; 11.187,-1.5 11.187,1.5

## 52760-0679 [mm]
pads (64):
  round 0.9 hole 0.9: 1(-10.86,0)
  rect 0.35x2.5 smd: 1(-9.207,-2.35) 2(-9.207,2.35) 3(-8.572,-2.35) 4(-8.572,2.35) 5(-7.938,-2.35) 6(-7.938,2.35) 7(-7.302,-2.35) 8(-7.302,2.35) 9(-6.667,-2.35) 10(-6.667,2.35) 11(-6.032,-2.35) 12(-6.032,2.35) 13(-5.397,-2.35) 14(-5.397,2.35) 15(-4.763,-2.35) 16(-4.763,2.35) 17(-4.127,-2.35) 18(-4.127,2.35) 19(-3.492,-2.35) 20(-3.492,2.35) 21(-2.857,-2.35) 22(-2.857,2.35) 23(-2.222,-2.35) 24(-2.222,2.35) 25(-1.587,-2.35) 26(-1.587,2.35) 27(-0.953,-2.35) 28(-0.953,2.35) 29(-0.318,-2.35) 30(-0.318,2.35) 31(0.318,-2.35) 32(0.318,2.35) 33(0.953,-2.35) 34(0.953,2.35) 35(1.587,-2.35) 36(1.587,2.35) 37(2.222,-2.35) 38(2.222,2.35) 39(2.857,-2.35) 40(2.857,2.35) 41(3.492,-2.35) 42(3.492,2.35) 43(4.127,-2.35) 44(4.127,2.35) 45(4.763,-2.35) 46(4.763,2.35) 47(5.397,-2.35) 48(5.397,2.35) 49(6.032,-2.35) 50(6.032,2.35) 51(6.667,-2.35) 52(6.667,2.35) 53(7.302,-2.35) 54(7.302,2.35) 55(7.938,-2.35) 56(7.938,2.35) 57(8.572,-2.35) 58(8.572,2.35) 59(9.207,-2.35) 60(9.207,2.35)
  round 0.7 hole 0.7: 1(10.86,0)
  rect 2.5x2 smd: M1(-12.9,0) M2(12.9,0)
Top Overlay:
  lines w0.203: -12.775,-1.5 -13.375,-1.5 -13.375,-1.9 -12.175,-3.1 -11.375,-3.1 -11.375,-2.4 ; -12.775,1.5 -13.375,1.5 -13.375,3.1 -11.375,3.1 -11.375,2.4 ; -9.775,-2 -11.525,-2 -11.525,0 -10.775,0 -10.775,2 -9.775,2 ; -9.775,-1 cw(c-9.775,-0.75) -10.025,-0.75 -10.025,0.75 cw(c-9.775,0.75) -9.775,1 ; 9.775,-2 11.525,-2 11.525,0 10.775,0 10.775,2 9.775,2 ; 9.775,-1 ccw(c9.775,-0.75) 10.025,-0.75 10.025,0.75 ccw(c9.775,0.75) 9.775,1 ; 11.375,-2.4 11.375,-3.1 13.375,-3.1 13.375,-1.5 12.775,-1.5 ; 11.375,2.4 11.375,3.1 13.375,3.1 13.375,1.5 12.775,1.5
Top Solder:
  rectangle: -9.407,-3.625 -9.008,-1.075
  region: -9.008,3.625 -9.407,3.625 -9.407,1.075 -9.008,1.075
  rectangle: -8.772,-3.625 -8.373,-1.075
  region: -8.373,3.625 -8.772,3.625 -8.772,1.075 -8.373,1.075
  rectangle: -8.137,-3.625 -7.738,-1.075
  region: -7.738,3.625 -8.137,3.625 -8.137,1.075 -7.738,1.075
  rectangle: -7.502,-3.625 -7.103,-1.075
  region: -7.103,3.625 -7.502,3.625 -7.502,1.075 -7.103,1.075
  rectangle: -6.867,-3.625 -6.468,-1.075
  region: -6.468,3.625 -6.867,3.625 -6.867,1.075 -6.468,1.075
  rectangle: -6.232,-3.625 -5.833,-1.075
  region: -5.833,3.625 -6.232,3.625 -6.232,1.075 -5.833,1.075
  rectangle: -5.597,-3.625 -5.198,-1.075
  region: -5.198,3.625 -5.597,3.625 -5.597,1.075 -5.198,1.075
  rectangle: -4.962,-3.625 -4.563,-1.075
  region: -4.563,3.625 -4.962,3.625 -4.962,1.075 -4.563,1.075
  rectangle: -4.327,-3.625 -3.928,-1.075
  region: -3.928,3.625 -4.327,3.625 -4.327,1.075 -3.928,1.075
  rectangle: -3.692,-3.625 -3.293,-1.075
  region: -3.293,3.625 -3.692,3.625 -3.692,1.075 -3.293,1.075
  rectangle: -3.057,-3.625 -2.658,-1.075
  region: -2.658,3.625 -3.057,3.625 -3.057,1.075 -2.658,1.075
  rectangle: -2.422,-3.625 -2.023,-1.075
  region: -2.023,3.625 -2.422,3.625 -2.422,1.075 -2.023,1.075
  rectangle: -1.787,-3.625 -1.388,-1.075
  region: -1.388,3.625 -1.787,3.625 -1.787,1.075 -1.388,1.075
  rectangle: -1.152,-3.625 -0.753,-1.075
  region: -0.753,3.625 -1.152,3.625 -1.152,1.075 -0.753,1.075
  rectangle: -0.517,-3.625 -0.118,-1.075
  region: -0.118,3.625 -0.517,3.625 -0.517,1.075 -0.118,1.075
  rectangle: 0.118,-3.625 0.517,-1.075
  region: 0.517,3.625 0.118,3.625 0.118,1.075 0.517,1.075
  rectangle: 0.753,-3.625 1.152,-1.075
  region: 1.152,3.625 0.753,3.625 0.753,1.075 1.152,1.075
  rectangle: 1.388,-3.625 1.787,-1.075
  region: 1.787,3.625 1.388,3.625 1.388,1.075 1.787,1.075
  rectangle: 2.023,-3.625 2.422,-1.075
  region: 2.422,3.625 2.023,3.625 2.023,1.075 2.422,1.075
  rectangle: 2.658,-3.625 3.057,-1.075
  region: 3.057,3.625 2.658,3.625 2.658,1.075 3.057,1.075
  rectangle: 3.293,-3.625 3.692,-1.075
  region: 3.692,3.625 3.293,3.625 3.293,1.075 3.692,1.075
  rectangle: 3.928,-3.625 4.327,-1.075
  region: 4.327,3.625 3.928,3.625 3.928,1.075 4.327,1.075
  rectangle: 4.563,-3.625 4.962,-1.075
  region: 4.962,3.625 4.563,3.625 4.563,1.075 4.962,1.075
  rectangle: 5.198,-3.625 5.597,-1.075
  region: 5.597,3.625 5.198,3.625 5.198,1.075 5.597,1.075
  rectangle: 5.833,-3.625 6.232,-1.075
  region: 6.232,3.625 5.833,3.625 5.833,1.075 6.232,1.075
  rectangle: 6.468,-3.625 6.867,-1.075
  region: 6.867,3.625 6.468,3.625 6.468,1.075 6.867,1.075
  rectangle: 7.103,-3.625 7.502,-1.075
  region: 7.502,3.625 7.103,3.625 7.103,1.075 7.502,1.075
  rectangle: 7.738,-3.625 8.137,-1.075
  region: 8.137,3.625 7.738,3.625 7.738,1.075 8.137,1.075
  rectangle: 8.373,-3.625 8.772,-1.075
  region: 8.772,3.625 8.373,3.625 8.373,1.075 8.772,1.075
  rectangle: 9.008,-3.625 9.407,-1.075
  region: 9.407,3.625 9.008,3.625 9.008,1.075 9.407,1.075
Mechanical 16:
  rectangle: -9.358,-3.1 -9.057,-2.375
  region: -9.057,3.1 -9.358,3.1 -9.358,2.375 -9.057,2.375
  rectangle: -8.723,-3.1 -8.422,-2.375
  region: -8.422,3.1 -8.723,3.1 -8.723,2.375 -8.422,2.375
  rectangle: -8.088,-3.1 -7.787,-2.375
  region: -7.787,3.1 -8.088,3.1 -8.088,2.375 -7.787,2.375
  rectangle: -7.453,-3.1 -7.152,-2.375
  region: -7.152,3.1 -7.453,3.1 -7.453,2.375 -7.152,2.375
  rectangle: -6.818,-3.1 -6.517,-2.375
  region: -6.517,3.1 -6.818,3.1 -6.818,2.375 -6.517,2.375
  rectangle: -6.183,-3.1 -5.882,-2.375
  region: -5.882,3.1 -6.183,3.1 -6.183,2.375 -5.882,2.375
  rectangle: -5.548,-3.1 -5.247,-2.375
  region: -5.247,3.1 -5.548,3.1 -5.548,2.375 -5.247,2.375
  rectangle: -4.913,-3.1 -4.612,-2.375
  region: -4.612,3.1 -4.913,3.1 -4.913,2.375 -4.612,2.375
  rectangle: -4.278,-3.1 -3.977,-2.375
  region: -3.977,3.1 -4.278,3.1 -4.278,2.375 -3.977,2.375
  rectangle: -3.643,-3.1 -3.342,-2.375
  region: -3.342,3.1 -3.643,3.1 -3.643,2.375 -3.342,2.375
  rectangle: -3.008,-3.1 -2.707,-2.375
  region: -2.707,3.1 -3.008,3.1 -3.008,2.375 -2.707,2.375
  rectangle: -2.373,-3.1 -2.072,-2.375
  region: -2.072,3.1 -2.373,3.1 -2.373,2.375 -2.072,2.375
  rectangle: -1.738,-3.1 -1.437,-2.375
  region: -1.437,3.1 -1.738,3.1 -1.738,2.375 -1.437,2.375
  rectangle: -1.103,-3.1 -0.802,-2.375
  region: -0.802,3.1 -1.103,3.1 -1.103,2.375 -0.802,2.375
  rectangle: -0.468,-3.1 -0.167,-2.375
  region: -0.167,3.1 -0.468,3.1 -0.468,2.375 -0.167,2.375
  rectangle: 0.167,-3.1 0.468,-2.375
  region: 0.468,3.1 0.167,3.1 0.167,2.375 0.468,2.375
  rectangle: 0.802,-3.1 1.103,-2.375
  region: 1.103,3.1 0.802,3.1 0.802,2.375 1.103,2.375
  rectangle: 1.437,-3.1 1.738,-2.375
  region: 1.738,3.1 1.437,3.1 1.437,2.375 1.738,2.375
  rectangle: 2.072,-3.1 2.373,-2.375
  region: 2.373,3.1 2.072,3.1 2.072,2.375 2.373,2.375
  rectangle: 2.707,-3.1 3.008,-2.375
  region: 3.008,3.1 2.707,3.1 2.707,2.375 3.008,2.375
  rectangle: 3.342,-3.1 3.643,-2.375
  region: 3.643,3.1 3.342,3.1 3.342,2.375 3.643,2.375
  rectangle: 3.977,-3.1 4.278,-2.375
  region: 4.278,3.1 3.977,3.1 3.977,2.375 4.278,2.375
  rectangle: 4.612,-3.1 4.913,-2.375
  region: 4.913,3.1 4.612,3.1 4.612,2.375 4.913,2.375
  rectangle: 5.247,-3.1 5.548,-2.375
  region: 5.548,3.1 5.247,3.1 5.247,2.375 5.548,2.375
  rectangle: 5.882,-3.1 6.183,-2.375
  region: 6.183,3.1 5.882,3.1 5.882,2.375 6.183,2.375
  rectangle: 6.517,-3.1 6.818,-2.375
  region: 6.818,3.1 6.517,3.1 6.517,2.375 6.818,2.375
  rectangle: 7.152,-3.1 7.453,-2.375
  region: 7.453,3.1 7.152,3.1 7.152,2.375 7.453,2.375
  rectangle: 7.787,-3.1 8.088,-2.375
  region: 8.088,3.1 7.787,3.1 7.787,2.375 8.088,2.375
  rectangle: 8.422,-3.1 8.723,-2.375
  region: 8.723,3.1 8.422,3.1 8.422,2.375 8.723,2.375
  rectangle: 9.057,-3.1 9.358,-2.375
  region: 9.358,3.1 9.057,3.1 9.057,2.375 9.358,2.375
  lines w0.203: -12.775,-1.5 -12.775,1.5 ; -11.375,-2.4 11.375,-2.4 ; -11.375,2.4 11.375,2.4 ; -9.775,-2 9.775,-2 ; -9.775,-1 9.775,-1 ; -9.775,1 9.775,1 ; -9.775,2 9.775,2 ; 12.775,-1.5 12.775,1.5

## 52760-0779 [mm]
pads (74):
  round 0.9 hole 0.9: 1(-12.448,0)
  rect 0.35x2.5 smd: 1(-10.795,-2.35) 2(-10.795,2.35) 3(-10.16,-2.35) 4(-10.16,2.35) 5(-9.525,-2.35) 6(-9.525,2.35) 7(-8.89,-2.35) 8(-8.89,2.35) 9(-8.255,-2.35) 10(-8.255,2.35) 11(-7.62,-2.35) 12(-7.62,2.35) 13(-6.985,-2.35) 14(-6.985,2.35) 15(-6.35,-2.35) 16(-6.35,2.35) 17(-5.715,-2.35) 18(-5.715,2.35) 19(-5.08,-2.35) 20(-5.08,2.35) 21(-4.445,-2.35) 22(-4.445,2.35) 23(-3.81,-2.35) 24(-3.81,2.35) 25(-3.175,-2.35) 26(-3.175,2.35) 27(-2.54,-2.35) 28(-2.54,2.35) 29(-1.905,-2.35) 30(-1.905,2.35) 31(-1.27,-2.35) 32(-1.27,2.35) 33(-0.635,-2.35) 34(-0.635,2.35) 35(0,-2.35) 36(0,2.35) 37(0.635,-2.35) 38(0.635,2.35) 39(1.27,-2.35) 40(1.27,2.35) 41(1.905,-2.35) 42(1.905,2.35) 43(2.54,-2.35) 44(2.54,2.35) 45(3.175,-2.35) 46(3.175,2.35) 47(3.81,-2.35) 48(3.81,2.35) 49(4.445,-2.35) 50(4.445,2.35) 51(5.08,-2.35) 52(5.08,2.35) 53(5.715,-2.35) 54(5.715,2.35) 55(6.35,-2.35) 56(6.35,2.35) 57(6.985,-2.35) 58(6.985,2.35) 59(7.62,-2.35) 60(7.62,2.35) 61(8.255,-2.35) 62(8.255,2.35) 63(8.89,-2.35) 64(8.89,2.35) 65(9.525,-2.35) 66(9.525,2.35) 67(10.16,-2.35) 68(10.16,2.35) 69(10.795,-2.35) 70(10.795,2.35)
  round 0.7 hole 0.7: 1(12.448,0)
  rect 2.5x2 smd: M1(-14.487,0) M2(14.487,0)
Top Overlay:
  lines w0.203: -14.362,-1.5 -14.962,-1.5 -14.962,-1.9 -13.762,-3.1 -12.962,-3.1 -12.962,-2.4 ; -14.362,1.5 -14.962,1.5 -14.962,3.1 -12.962,3.1 -12.962,2.4 ; -11.362,-2 -13.112,-2 -13.112,0 -12.362,0 -12.362,2 -11.362,2 ; -11.362,-1 cw(c-11.363,-0.75) -11.613,-0.75 -11.613,0.75 cw(c-11.363,0.75) -11.362,1 ; 11.362,-2 13.112,-2 13.112,0 12.362,0 12.362,2 11.362,2 ; 11.362,-1 ccw(c11.363,-0.75) 11.613,-0.75 11.613,0.75 ccw(c11.363,0.75) 11.362,1 ; 12.962,-2.4 12.962,-3.1 14.962,-3.1 14.962,-1.5 14.362,-1.5 ; 12.962,2.4 12.962,3.1 14.962,3.1 14.962,1.5 14.362,1.5
Top Solder:
  rectangle: -10.995,-3.625 -10.595,-1.075
  region: -10.595,3.625 -10.995,3.625 -10.995,1.075 -10.595,1.075
  rectangle: -10.36,-3.625 -9.96,-1.075
  region: -9.96,3.625 -10.36,3.625 -10.36,1.075 -9.96,1.075
  rectangle: -9.725,-3.625 -9.325,-1.075
  region: -9.325,3.625 -9.725,3.625 -9.725,1.075 -9.325,1.075
  rectangle: -9.09,-3.625 -8.69,-1.075
  region: -8.69,3.625 -9.09,3.625 -9.09,1.075 -8.69,1.075
  rectangle: -8.455,-3.625 -8.055,-1.075
  region: -8.055,3.625 -8.455,3.625 -8.455,1.075 -8.055,1.075
  rectangle: -7.82,-3.625 -7.42,-1.075
  region: -7.42,3.625 -7.82,3.625 -7.82,1.075 -7.42,1.075
  rectangle: -7.185,-3.625 -6.785,-1.075
  region: -6.785,3.625 -7.185,3.625 -7.185,1.075 -6.785,1.075
  rectangle: -6.55,-3.625 -6.15,-1.075
  region: -6.15,3.625 -6.55,3.625 -6.55,1.075 -6.15,1.075
  rectangle: -5.915,-3.625 -5.515,-1.075
  region: -5.515,3.625 -5.915,3.625 -5.915,1.075 -5.515,1.075
  rectangle: -5.28,-3.625 -4.88,-1.075
  region: -4.88,3.625 -5.28,3.625 -5.28,1.075 -4.88,1.075
  rectangle: -4.645,-3.625 -4.245,-1.075
  region: -4.245,3.625 -4.645,3.625 -4.645,1.075 -4.245,1.075
  rectangle: -4.01,-3.625 -3.61,-1.075
  region: -3.61,3.625 -4.01,3.625 -4.01,1.075 -3.61,1.075
  rectangle: -3.375,-3.625 -2.975,-1.075
  region: -2.975,3.625 -3.375,3.625 -3.375,1.075 -2.975,1.075
  rectangle: -2.74,-3.625 -2.34,-1.075
  region: -2.34,3.625 -2.74,3.625 -2.74,1.075 -2.34,1.075
  rectangle: -2.105,-3.625 -1.705,-1.075
  region: -1.705,3.625 -2.105,3.625 -2.105,1.075 -1.705,1.075
  rectangle: -1.47,-3.625 -1.07,-1.075
  region: -1.07,3.625 -1.47,3.625 -1.47,1.075 -1.07,1.075
  rectangle: -0.835,-3.625 -0.435,-1.075
  region: -0.435,3.625 -0.835,3.625 -0.835,1.075 -0.435,1.075
  rectangle: -0.2,-3.625 0.2,-1.075
  region: 0.2,3.625 -0.2,3.625 -0.2,1.075 0.2,1.075
  rectangle: 0.435,-3.625 0.835,-1.075
  region: 0.835,3.625 0.435,3.625 0.435,1.075 0.835,1.075
  rectangle: 1.07,-3.625 1.47,-1.075
  region: 1.47,3.625 1.07,3.625 1.07,1.075 1.47,1.075
  rectangle: 1.705,-3.625 2.105,-1.075
  region: 2.105,3.625 1.705,3.625 1.705,1.075 2.105,1.075
  rectangle: 2.34,-3.625 2.74,-1.075
  region: 2.74,3.625 2.34,3.625 2.34,1.075 2.74,1.075
  rectangle: 2.975,-3.625 3.375,-1.075
  region: 3.375,3.625 2.975,3.625 2.975,1.075 3.375,1.075
  rectangle: 3.61,-3.625 4.01,-1.075
  region: 4.01,3.625 3.61,3.625 3.61,1.075 4.01,1.075
  rectangle: 4.245,-3.625 4.645,-1.075
  region: 4.645,3.625 4.245,3.625 4.245,1.075 4.645,1.075
  rectangle: 4.88,-3.625 5.28,-1.075
  region: 5.28,3.625 4.88,3.625 4.88,1.075 5.28,1.075
  rectangle: 5.515,-3.625 5.915,-1.075
  region: 5.915,3.625 5.515,3.625 5.515,1.075 5.915,1.075
  rectangle: 6.15,-3.625 6.55,-1.075
  region: 6.55,3.625 6.15,3.625 6.15,1.075 6.55,1.075
  rectangle: 6.785,-3.625 7.185,-1.075
  region: 7.185,3.625 6.785,3.625 6.785,1.075 7.185,1.075
  rectangle: 7.42,-3.625 7.82,-1.075
  region: 7.82,3.625 7.42,3.625 7.42,1.075 7.82,1.075
  rectangle: 8.055,-3.625 8.455,-1.075
  region: 8.455,3.625 8.055,3.625 8.055,1.075 8.455,1.075
  rectangle: 8.69,-3.625 9.09,-1.075
  region: 9.09,3.625 8.69,3.625 8.69,1.075 9.09,1.075
  rectangle: 9.325,-3.625 9.725,-1.075
  region: 9.725,3.625 9.325,3.625 9.325,1.075 9.725,1.075
  rectangle: 9.96,-3.625 10.36,-1.075
  region: 10.36,3.625 9.96,3.625 9.96,1.075 10.36,1.075
  rectangle: 10.595,-3.625 10.995,-1.075
  region: 10.995,3.625 10.595,3.625 10.595,1.075 10.995,1.075
Mechanical 16:
  rectangle: -10.945,-3.1 -10.645,-2.375
  region: -10.645,3.1 -10.945,3.1 -10.945,2.375 -10.645,2.375
  rectangle: -10.31,-3.1 -10.01,-2.375
  region: -10.01,3.1 -10.31,3.1 -10.31,2.375 -10.01,2.375
  rectangle: -9.675,-3.1 -9.375,-2.375
  region: -9.375,3.1 -9.675,3.1 -9.675,2.375 -9.375,2.375
  rectangle: -9.04,-3.1 -8.74,-2.375
  region: -8.74,3.1 -9.04,3.1 -9.04,2.375 -8.74,2.375
  rectangle: -8.405,-3.1 -8.105,-2.375
  region: -8.105,3.1 -8.405,3.1 -8.405,2.375 -8.105,2.375
  rectangle: -7.77,-3.1 -7.47,-2.375
  region: -7.47,3.1 -7.77,3.1 -7.77,2.375 -7.47,2.375
  rectangle: -7.135,-3.1 -6.835,-2.375
  region: -6.835,3.1 -7.135,3.1 -7.135,2.375 -6.835,2.375
  rectangle: -6.5,-3.1 -6.2,-2.375
  region: -6.2,3.1 -6.5,3.1 -6.5,2.375 -6.2,2.375
  rectangle: -5.865,-3.1 -5.565,-2.375
  region: -5.565,3.1 -5.865,3.1 -5.865,2.375 -5.565,2.375
  rectangle: -5.23,-3.1 -4.93,-2.375
  region: -4.93,3.1 -5.23,3.1 -5.23,2.375 -4.93,2.375
  rectangle: -4.595,-3.1 -4.295,-2.375
  region: -4.295,3.1 -4.595,3.1 -4.595,2.375 -4.295,2.375
  rectangle: -3.96,-3.1 -3.66,-2.375
  region: -3.66,3.1 -3.96,3.1 -3.96,2.375 -3.66,2.375
  rectangle: -3.325,-3.1 -3.025,-2.375
  region: -3.025,3.1 -3.325,3.1 -3.325,2.375 -3.025,2.375
  rectangle: -2.69,-3.1 -2.39,-2.375
  region: -2.39,3.1 -2.69,3.1 -2.69,2.375 -2.39,2.375
  rectangle: -2.055,-3.1 -1.755,-2.375
  region: -1.755,3.1 -2.055,3.1 -2.055,2.375 -1.755,2.375
  rectangle: -1.42,-3.1 -1.12,-2.375
  region: -1.12,3.1 -1.42,3.1 -1.42,2.375 -1.12,2.375
  rectangle: -0.785,-3.1 -0.485,-2.375
  region: -0.485,3.1 -0.785,3.1 -0.785,2.375 -0.485,2.375
  rectangle: -0.15,-3.1 0.15,-2.375
  region: 0.15,3.1 -0.15,3.1 -0.15,2.375 0.15,2.375
  rectangle: 0.485,-3.1 0.785,-2.375
  region: 0.785,3.1 0.485,3.1 0.485,2.375 0.785,2.375
  rectangle: 1.12,-3.1 1.42,-2.375
  region: 1.42,3.1 1.12,3.1 1.12,2.375 1.42,2.375
  rectangle: 1.755,-3.1 2.055,-2.375
  region: 2.055,3.1 1.755,3.1 1.755,2.375 2.055,2.375
  rectangle: 2.39,-3.1 2.69,-2.375
  region: 2.69,3.1 2.39,3.1 2.39,2.375 2.69,2.375
  rectangle: 3.025,-3.1 3.325,-2.375
  region: 3.325,3.1 3.025,3.1 3.025,2.375 3.325,2.375
  rectangle: 3.66,-3.1 3.96,-2.375
  region: 3.96,3.1 3.66,3.1 3.66,2.375 3.96,2.375
  rectangle: 4.295,-3.1 4.595,-2.375
  region: 4.595,3.1 4.295,3.1 4.295,2.375 4.595,2.375
  rectangle: 4.93,-3.1 5.23,-2.375
  region: 5.23,3.1 4.93,3.1 4.93,2.375 5.23,2.375
  rectangle: 5.565,-3.1 5.865,-2.375
  region: 5.865,3.1 5.565,3.1 5.565,2.375 5.865,2.375
  rectangle: 6.2,-3.1 6.5,-2.375
  region: 6.5,3.1 6.2,3.1 6.2,2.375 6.5,2.375
  rectangle: 6.835,-3.1 7.135,-2.375
  region: 7.135,3.1 6.835,3.1 6.835,2.375 7.135,2.375
  rectangle: 7.47,-3.1 7.77,-2.375
  region: 7.77,3.1 7.47,3.1 7.47,2.375 7.77,2.375
  rectangle: 8.105,-3.1 8.405,-2.375
  region: 8.405,3.1 8.105,3.1 8.105,2.375 8.405,2.375
  rectangle: 8.74,-3.1 9.04,-2.375
  region: 9.04,3.1 8.74,3.1 8.74,2.375 9.04,2.375
  rectangle: 9.375,-3.1 9.675,-2.375
  region: 9.675,3.1 9.375,3.1 9.375,2.375 9.675,2.375
  rectangle: 10.01,-3.1 10.31,-2.375
  region: 10.31,3.1 10.01,3.1 10.01,2.375 10.31,2.375
  rectangle: 10.645,-3.1 10.945,-2.375
  region: 10.945,3.1 10.645,3.1 10.645,2.375 10.945,2.375
  lines w0.203: -14.362,-1.5 -14.362,1.5 ; -12.962,-2.4 12.962,-2.4 ; -12.962,2.4 12.962,2.4 ; -11.362,-2 11.362,-2 ; -11.362,-1 11.362,-1 ; -11.362,1 11.362,1 ; -11.362,2 11.362,2 ; 14.362,-1.5 14.362,1.5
